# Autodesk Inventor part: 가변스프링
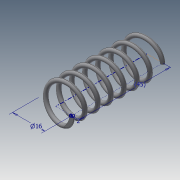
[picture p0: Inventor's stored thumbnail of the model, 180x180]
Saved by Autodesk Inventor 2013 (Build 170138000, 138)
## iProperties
Created: 2021-08
Part Number: 가변스프링
Material: Generic
Document SubType Name: Modeling
Designer: user
Density: 1 g/cm^3
Mass: 1.09309 g
Surface Area: 22.1028 cm^2
Volume: 1.09309 cm^3
Author: user
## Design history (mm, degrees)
sketch "스케치1"
  geometry: L1 (0, 0)-(8, 0); L2 (8, 0)-(8, 38); L3 (8, 38)-(0, 38); L4 (0, 38)-(0, 0); C1 r 1 at (8, 0)
  constraints: 8 end point, 2 parallel, 1 centre point, 1 coincident, 1 horizontal, 1 perpendicular
  dimensions: "d0" = 2 diameter of C1; "d1" = 38 distance of L1.end L2.end (derived); "d2" = 16 diameter of L2 L4
node "작업 평면1"
node "작업 평면2"
feature "코일2" pitch "d17" = 10; turns "d19" = 7; dims "d18" = 38 (= d1), "d20" = 0, angle "d21" = 90 deg, angle "d22" = 90 deg, "d23" = 0, "d24" = 0
node "작업 평면3"
sketch "스케치4"
  geometry: L1 (7, 0)-(9, 0) reference; 1 further point
  constraints: 1 horizontal alignment
extrude "돌출3" cut sketch "스케치4" distance "d26" = 10; taper "d27" = 0 deg
node "작업 평면4"
sketch "스케치5"
  geometry: L1 (-1, 0)-(1, 0) reference; 1 further point
  constraints: 1 horizontal alignment
extrude "돌출4" cut sketch "스케치5" distance "d29" = 10; taper "d30" = 0 deg
node "솔리드2"
node "절단 모서리 투영3"
node "절단 모서리 투영4"
other parameters: "d25" = 90 deg, "d28" = 90 deg
